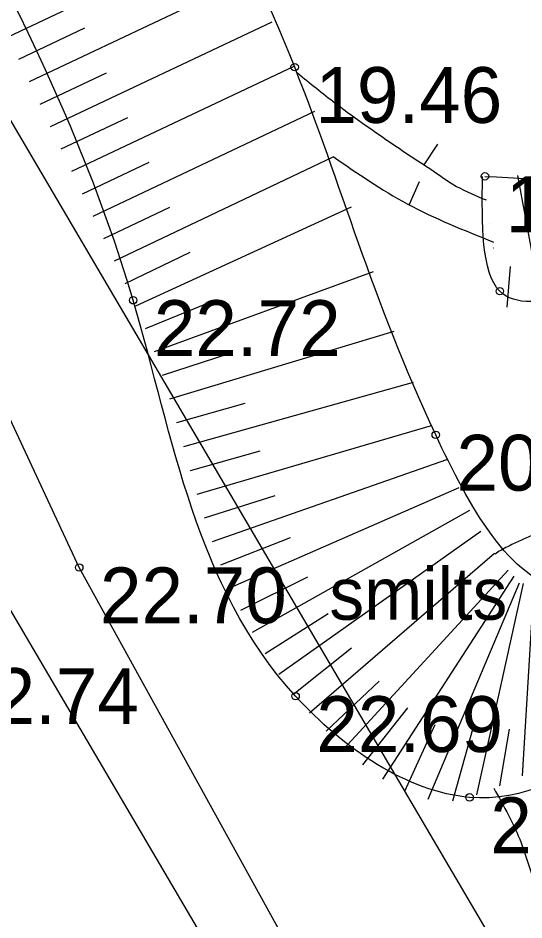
# Model space of a CAD drawing. Extents: x 521824 to 524158, y 294774 to 296228.
# Drawn here: x 522056.81 to 522067.01, y 295960.8 to 295978.98 of the extents above; entities that cross this region are included whole.
import ezdxf

# ---------------------------------------------------------------- set-up
doc = ezdxf.new("R2010")
doc.units = 0
for name, color, linetype in [('7315030100', 7, 'Continuous'), ('CELI_CMAL_####_####_#', 7, 'Continuous'), ('RELJ_AATZ_####_TKST_#', 7, 'Continuous'), ('RELJ_ELEM_####_####_#', 7, 'Continuous'), ('RELJ_HORZ_PAMT_####_#', 7, 'Continuous'), ('RELJ_HORZ_RESN_####_#', 7, 'Continuous'), ('RELJ_NOGA_####_####_#', 7, 'Continuous'), ('RELJ_NOGL_####_####_#', 7, 'Continuous'), ('TERT_IZMT_####_TKST_#', 7, 'Continuous')]:
    doc.layers.add(name, color=color, linetype=linetype)

msp = doc.modelspace()

# ---------------------------------------------------------------- linework, layer by layer
at = {"layer": '7315030100'}
msp.add_lwpolyline([(521982.6621484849, 296071.9435568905), (522030.78400000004, 296022.73900000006), (522033.5410000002, 296023.5089999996), (522041.3830000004, 296002.9110000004), (522075.3820000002, 295945.0490000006), (522118.8880000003, 295885.8499999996), (522163.66299999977, 295827.4399999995), (522159.46399999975, 295824.69800000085), (522114.8890000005, 295882.8479999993), (522071.2010000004, 295942.2949999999), (522036.86299999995, 296000.73299999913), (522028.99600000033, 296021.0460000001), (521979.24799999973, 296071.9199999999), (521979.2263936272, 296071.94480188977)], dxfattribs=at)
at = {"layer": 'CELI_CMAL_####_####_#'}
msp.add_lwpolyline([(522062.798, 295959.285), (522062.798, 295959.285), (522058.043, 295967.908), (522052.45, 295979.914), (522045.71900000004, 295994.345), (522039.629, 296007.129), (522036.52900000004, 296013.324), (522032.55600000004, 296024.949), (522023.76300000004, 296039.8020000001), (522021.40314783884, 296041.95388574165)], dxfattribs=at)
at = {"layer": 'RELJ_ELEM_####_####_#'}
for centre in [(522062.385, 295977.993), (522066.221, 295975.7910000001), (522066.521, 295973.4760000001), (522059.129, 295973.294), (522065.228, 295970.581), (522058.043, 295967.908), (522062.40400000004, 295965.313), (522065.911, 295963.274)]:
    msp.add_circle(centre, 0.075, dxfattribs=at)
at = {"layer": 'RELJ_HORZ_PAMT_####_#'}
msp.add_line((522065.2616334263, 295976.44287662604), (522064.98594110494, 295976.02575105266), dxfattribs=at)
for points in [[(522045.99916861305, 296008.93831280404), (522046.49453317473, 296008.92595232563), (522047.5569777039, 296008.9876608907), (522048.7352719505, 296009.16243659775), (522050.1086132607, 296009.5122674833), (522050.80903421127, 296009.67697573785), (522052.33978770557, 296009.89636299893), (522053.69336679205, 296010.1012961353), (522054.53584980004, 296010.3352620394), (522054.9958883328, 296010.3548022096), (522055.84819052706, 296010.24920471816), (522056.3615615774, 296010.05151829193), (522056.84400024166, 296009.7971695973), (522057.3232998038, 296009.54486659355), (522057.8272535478, 296009.35331723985), (522058.4626550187, 296009.22154380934), (522059.0393428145, 296009.16767079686), (522060.32236197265, 296008.9748978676), (522060.9463163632, 296008.77207442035), (522061.25375214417, 296008.6200969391), (522061.55810217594, 296008.42528266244), (522061.88262937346, 296008.0153098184), (522062.0218725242, 296007.52360985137), (522062.054247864, 296007.1621675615), (522062.0186516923, 296006.80134330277), (522061.4347738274, 296005.35546226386), (522061.1000413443, 296005.14011433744), (522060.7638870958, 296004.9331873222), (522060.08886997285, 296004.53638134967), (522058.7388979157, 296003.75345890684), (522057.7923461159, 296003.23430771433), (522057.3210422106, 296002.9524294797), (522057.0863706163, 296002.7883114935), (522056.96934082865, 296002.6982573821), (522056.8525382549, 296002.6020349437), (522056.58432951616, 296002.1029501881), (522056.5879277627, 296001.5314473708), (522056.8604757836, 296000.04847520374), (522057.2402849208, 295998.54283794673), (522057.7461206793, 295997.70973384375), (522058.03680635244, 295997.31723721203), (522058.30254747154, 295996.9097403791), (522059.0433495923, 295995.57643281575), (522059.75888167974, 295994.2297315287), (522060.1221947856, 295993.3378359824), (522060.4056172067, 295992.40603629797), (522060.729315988, 295991.49617859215), (522060.94382121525, 295991.06880489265), (522061.21345817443, 295990.6701089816), (522061.4902514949, 295990.3661353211), (522061.7928378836, 295990.09023884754), (522062.2517302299, 295989.6829543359), (522062.3961226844, 295989.5384086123), (522064.20845121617, 295987.6127990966), (522065.33782183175, 295986.41810940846), (522065.91800615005, 295985.833831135), (522066.5247454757, 295985.2675388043), (522067.24159352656, 295984.8808520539), (522068.07378551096, 295984.73408263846), (522068.9445075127, 295984.6568827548), (522069.37031292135, 295984.5911376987), (522069.776945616, 295984.47890459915), (522071.1625602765, 295983.9488713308), (522071.8369571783, 295983.6153994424), (522072.5070824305, 295983.18557463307), (522073.4447655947, 295982.3130629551), (522074.1896808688, 295981.2988836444), (522074.7592048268, 295980.2633860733), (522075.1707140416, 295979.3269196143), (522075.1459578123, 295979.0117688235), (522074.868774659, 295978.7091636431), (522073.88714736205, 295978.1248778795), (522072.8858717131, 295977.540637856), (522072.5841281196, 295977.23808985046), (522072.5249872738, 295976.9230191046), (522072.5995568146, 295976.687403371), (522072.71339548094, 295976.4217127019), (522073.00814262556, 295976.0044033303)], [(522064.82510563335, 295928.2791756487), (522064.78711655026, 295928.38549290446), (522064.1616114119, 295929.1073032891), (522063.3728918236, 295929.70611264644), (522062.65919595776, 295930.3170105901), (522062.25876198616, 295931.0750867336), (522062.2346441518, 295931.5228396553), (522062.2648391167, 295931.97685639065), (522062.44912482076, 295932.8715409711), (522062.63266130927, 295933.46287167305), (522062.86987207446, 295934.0526976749), (522063.0898956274, 295934.6414267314), (522063.2218704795, 295935.22946659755), (522063.12508164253, 295938.08761898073), (522062.2525315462, 295940.90174500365), (522060.67756972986, 295943.6813651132), (522059.6496061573, 295945.06121058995), (522058.473545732, 295946.43599975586), (522057.23901907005, 295947.6042419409), (522055.96648575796, 295948.4418250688), (522054.6350544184, 295948.98488778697), (522053.22383367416, 295949.26956874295), (522051.9272766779, 295949.18895789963), (522050.63008417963, 295948.81450551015), (522049.33250547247, 295948.39407477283), (522048.0347898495, 295948.1755288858), (522047.1542657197, 295948.1100891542), (522046.26764041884, 295948.07967492), (522045.3880689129, 295948.2625355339), (522044.9550392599, 295948.48964683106), (522044.7409328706, 295948.64687073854), (522044.5287061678, 295948.8369203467), (522044.10241917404, 295949.6774190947), (522044.2670966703, 295950.5524742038), (522044.47190412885, 295950.99059733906), (522044.69717438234, 295951.4171837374), (522044.9121479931, 295951.84627480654), (522045.08606552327, 295952.2919119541), (522045.32407232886, 295953.0785039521), (522046.00793187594, 295955.2470296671), (522046.7112961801, 295957.41220797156), (522047.4147983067, 295959.57668915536), (522048.0990713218, 295961.7431235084), (522047.9022227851, 295963.8266190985), (522047.0537889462, 295964.8845110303), (522046.1952892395, 295965.90749112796), (522044.4516487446, 295967.87574794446), (522040.88269908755, 295971.6906729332), (522040.78269798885, 295971.79704074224), (522034.73556157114, 295978.3328918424), (522033.5959316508, 295979.41468782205), (522032.94552574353, 295979.97614117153), (522032.4997665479, 295980.7227613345), (522031.9003481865, 295981.619972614), (522033.34310858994, 295980.81307497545), (522034.23418230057, 295980.93968649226), (522034.5147495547, 295981.284214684), (522034.9100943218, 295981.9222298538), (522035.1013901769, 295982.955814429), (522035.1524024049, 295983.92559748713), (522035.26717991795, 295985.01022327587), (522033.9390973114, 295986.07574398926), (522033.4434927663, 295986.17141088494), (522032.916313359, 295986.06417016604), (522032.16858402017, 295985.15407899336), (522031.86211369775, 295984.4423897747), (522031.55956677, 295982.8775716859), (522031.68299478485, 295982.0905882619), (522030.5416152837, 295982.4877882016), (522029.69968306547, 295982.7293382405), (522028.8610878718, 295983.02656173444), (522028.01960643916, 295983.3273787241), (522027.16901550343, 295983.5797092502), (522024.6873548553, 295984.1725223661), (522022.1791479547, 295984.6634106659), (522019.6656579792, 295985.2562258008), (522018.4135765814, 295985.6545595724), (522017.78986461, 295985.8903561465), (522017.16814810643, 295986.154819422), (522016.7172860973, 295986.46550843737), (522016.52468607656, 295986.66791604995), (522016.34695997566, 295986.89076055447), (522016.2654762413, 295987.76648707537), (522016.43304400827, 295987.9540466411)], [(522062.442418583, 295977.87533438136), (522063.2083504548, 295977.263876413), (522064.00107052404, 295976.6906286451), (522064.81589162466, 295976.1382248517), (522065.23012532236, 295975.86441249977), (522065.6481265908, 295975.58929880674), (522066.2428728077, 295975.3156127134)], [(522066.39629252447, 295963.4562464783), (522066.9486297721, 295962.3583067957), (522067.0053979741, 295962.1996183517), (522067.05728089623, 295962.03947144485), (522067.10959387, 295961.8795879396), (522067.1676522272, 295961.72168970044), (522067.4431851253, 295961.11550648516), (522067.66591271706, 295960.7517636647), (522068.0848112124, 295960.2384606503), (522068.5624973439, 295959.7645029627), (522069.0100830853, 295959.2730673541), (522069.33868041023, 295958.7073305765), (522069.4433804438, 295958.2790684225), (522069.7129823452, 295957.33001349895)]]:
    msp.add_spline(points, degree=3, dxfattribs=at)
at = {"layer": 'RELJ_HORZ_RESN_####_#'}
msp.add_line((522064.89215622, 295975.67966963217), (522064.6895693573, 295975.2225497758), dxfattribs=at)
for points in [[(522063.1605072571, 295976.1886159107), (522064.65278475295, 295975.23885201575), (522066.3924654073, 295974.4678585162)], [(522067.6314680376, 295968.7596691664), (522067.15025426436, 295968.545161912), (522066.9104552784, 295968.43601476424), (522066.6714993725, 295968.32472031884), (522066.5387011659, 295968.25107697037), (522066.422901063, 295968.1788368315)]]:
    msp.add_spline(points, degree=3, dxfattribs=at)
at = {"layer": 'RELJ_NOGA_####_####_#'}
for p, q in [((522056.61096246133, 295978.60444280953), (522061.03381589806, 295980.7019727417)), ((522057.0393130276, 295977.70083025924), (522061.48461344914, 295979.8031909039)), ((522057.46684986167, 295976.7968323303), (522061.9315092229, 295978.90834859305)), ((522056.8252136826, 295978.15267249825), (522058.15514437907, 295978.7833896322)), ((522057.8943866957, 295975.8928344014), (522062.37553413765, 295978.012148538)), ((522057.25308144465, 295977.24883129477), (522058.58968567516, 295977.8809649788)), ((522058.3222521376, 295974.9889920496), (522062.79110669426, 295977.10699122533)), ((522057.68061827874, 295976.3448333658), (522059.0226107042, 295976.97951534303)), ((522058.751246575, 295974.0856850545), (522063.16279684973, 295976.1824757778)), ((522058.1081551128, 295975.44083543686), (522059.4528216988, 295976.07678213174)), ((522067.3895778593, 295973.0857782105), (522066.88323286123, 295975.80853581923)), ((522058.53660923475, 295974.5372720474), (522059.8697762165, 295975.17092053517)), ((522059.18126654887, 295973.1828683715), (522063.5280054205, 295975.17585785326)), ((522066.3139548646, 295974.8454556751), (522066.31425149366, 295974.8455005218)), ((522066.38869939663, 295974.35107398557), (522066.38968816, 295974.35122347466)), ((522058.96653300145, 295973.6344072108), (522060.2769806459, 295974.2598478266)), ((522066.67069757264, 295973.1526822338), (522066.73602315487, 295973.97357005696)), ((522059.56011725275, 295972.257748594), (522063.97208006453, 295973.87580118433)), ((522066.4634439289, 295973.8566922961), (522066.46374055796, 295973.85673714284)), ((522059.3806715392, 295972.7244017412), (522060.69387797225, 295973.25918768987)), ((522066.5459537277, 295973.3638613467), (522066.54690855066, 295973.3641585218)), ((522059.8722598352, 295971.3078525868), (522064.3887007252, 295972.6731681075)), ((522059.72277872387, 295971.7849719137), (522061.062356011, 295972.22277314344)), ((522060.14814492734, 295970.3466815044), (522064.7769421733, 295971.63998041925)), ((522060.01269016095, 295970.8279832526), (522061.38568053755, 295971.2174201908)), ((522060.4215978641, 295969.38480657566), (522065.1422974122, 295970.77053921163)), ((522060.2830515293, 295969.8652253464), (522061.6873835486, 295970.26016519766)), ((522060.7258929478, 295968.4323327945), (522065.4494787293, 295970.0809435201)), ((522061.0898559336, 295967.50119050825), (522065.6982648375, 295969.5169034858)), ((522060.56804047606, 295968.9067425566), (522061.9891347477, 295969.35781530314)), ((522061.53389885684, 295966.60562681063), (522065.9135825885, 295969.0602215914)), ((522060.89888555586, 295967.96324231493), (522062.3020425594, 295968.5116153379)), ((522062.06715105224, 295965.7602291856), (522066.13627514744, 295968.6363786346)), ((522062.68571148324, 295964.975016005), (522066.4097838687, 295968.19755639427)), ((522063.37893039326, 295964.25501200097), (522066.6848812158, 295967.8539446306)), ((522061.301054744, 295967.0480394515), (522062.65202407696, 295967.71971867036)), ((522064.1647716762, 295963.6387032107), (522066.8090984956, 295967.73161283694)), ((522065.07567484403, 295963.2386844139), (522066.91531961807, 295967.5977217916)), ((522066.0553207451, 295963.32520900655), (522066.99829063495, 295967.5841171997)), ((522066.9775541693, 295963.7109513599), (522067.2068468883, 295967.4751474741)), ((522061.7893039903, 295966.1758488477), (522063.05846480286, 295966.978361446)), ((522062.3667068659, 295965.35997206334), (522063.5316160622, 295966.2848433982)), ((522063.02237794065, 295964.6054241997), (522064.0873344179, 295965.61856428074)), ((522063.75831058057, 295963.9295188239), (522064.6625436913, 295965.08035396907)), ((522064.60300242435, 295963.39885503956), (522065.2191086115, 295964.7445683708)), ((522065.5724687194, 295963.20257539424), (522065.9756347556, 295964.6508907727)), ((522066.52079115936, 295963.5076526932), (522066.71331878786, 295964.6508907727))]:
    msp.add_line(p, q, dxfattribs=at)
for points in [[(522076.37200000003, 295971.107), (522071.771, 295966.998), (522065.911, 295963.274), (522062.40400000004, 295965.313), (522059.129, 295973.294), (522053.39900000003, 295985.16500000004), (522047.568, 295996.23000000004), (522043.494, 296004.5300000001), (522040.94, 296006.195), (522036.39200000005, 296017.202), (522035.81700000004, 296019.88800000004)], [(522079.21900000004, 295978.576), (522076.38100000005, 295975.043), (522070.223, 295974.179), (522066.521, 295973.4760000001), (522066.17100000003, 295975.791)]]:
    msp.add_spline(points, degree=3, dxfattribs=at)
at = {"layer": 'RELJ_NOGL_####_####_#'}
for points in [[(522076.37200000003, 295971.107), (522070.977, 295968.83900000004), (522067.829, 295967.468), (522065.228, 295970.581), (522062.385, 295977.993), (522058.471, 295985.85500000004), (522053.108, 295997.011), (522048.49000000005, 296007.412), (522045.5405427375, 296009.21934609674)], [(522066.221, 295975.7910000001), (522073.416, 295976.088), (522079.21900000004, 295978.576)]]:
    msp.add_spline(points, degree=3, dxfattribs=at)

# ---------------------------------------------------------------- texts
at = {"layer": 'RELJ_AATZ_####_TKST_#'}
for s, p in [(' 19.46', (522062.385, 295976.868)), (' 19.21', (522066.221, 295974.6660000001)), (' 22.72', (522059.129, 295972.169)), (' 20.24', (522065.228, 295969.456)), (' 22.70', (522058.043, 295966.783)), (' 22.74', (522055.06200000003, 295964.7530000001)), (' 22.69', (522062.40400000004, 295964.188)), (' 22.67', (522065.911, 295962.149))]:
    msp.add_text(s, height=1.125, dxfattribs=at).set_placement(p)
at = {"layer": 'TERT_IZMT_####_TKST_#'}
msp.add_text('smilts', height=1.0499999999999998, dxfattribs=at).set_placement((522063.083715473, 295966.85398381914))

doc.saveas('drawing.dxf')
